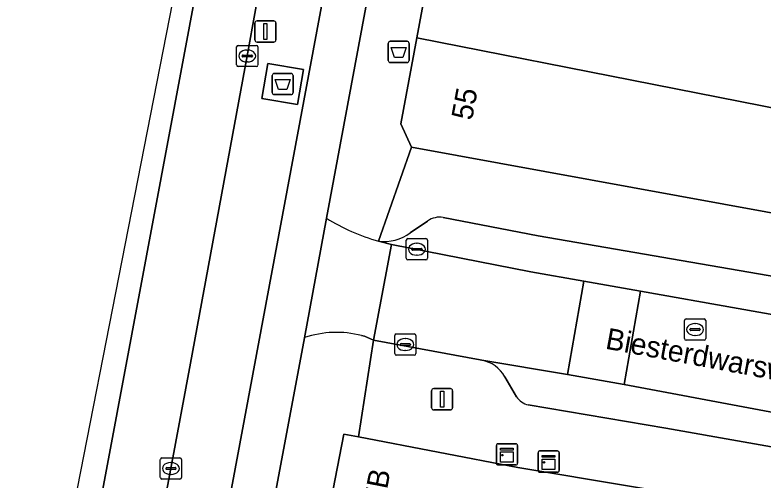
# Model space of a CAD drawing. Extents: x 161838 to 162344, y 381620 to 382160.
# Drawn here: x 161893.72 to 161929.05, y 381932.12 to 381954.06 of the extents above; entities that cross this region are included whole.
import ezdxf

# ---------------------------------------------------------------- set-up
doc = ezdxf.new("R2010")
doc.units = 0
for name, color, linetype in [('IMGEO_Afval_apart_plaats', 7, 'Continuous'), ('IMGEO_Afvalbak', 7, 'Continuous'), ('IMGEO_Berm_open', 7, 'Continuous'), ('IMGEO_Fietspad_gesloten', 7, 'Continuous'), ('IMGEO_Kast', 7, 'Continuous'), ('IMGEO_Kolk', 7, 'Continuous'), ('IMGEO_Lichtmast', 7, 'Continuous'), ('IMGEO_Muur', 7, 'Continuous'), ('IMGEO_Openbare_ruimte_label', 7, 'Continuous'), ('IMGEO_OVBaan_gesloten', 7, 'Continuous'), ('IMGEO_Pand', 7, 'Continuous'), ('IMGEO_Pand_nummerreeks', 7, 'Continuous'), ('IMGEO_Parkeervlak_open', 7, 'Continuous'), ('IMGEO_Rijbaan_lokaal_gesloten', 7, 'Continuous'), ('IMGEO_Rijbaan_lokaal_open', 7, 'Continuous'), ('IMGEO_Rioolput', 7, 'Continuous'), ('IMGEO_Voetpad_gesloten', 7, 'Continuous'), ('IMGEO_Voetpad_open', 7, 'Continuous')]:
    doc.layers.add(name, color=color, linetype=linetype)

msp = doc.modelspace()

# ---------------------------------------------------------------- linework, layer by layer
at = {"layer": 'IMGEO_Afval_apart_plaats'}
for p, q in [((161905.866, 381950.4), (161905.866, 381951.2)), ((161905.866, 381951.2), (161905.866, 381950.4)), ((161905.966, 381951.3), (161906.756, 381951.3)), ((161906.756, 381951.3), (161905.966, 381951.3)), ((161906.856, 381951.2), (161906.856, 381950.4)), ((161906.856, 381950.4), (161906.856, 381951.2)), ((161906.756, 381950.3), (161905.966, 381950.3)), ((161905.966, 381950.3), (161906.756, 381950.3))]:
    msp.add_line(p, q, dxfattribs=at)
msp.add_lwpolyline([(161906.009, 381951.014), (161906.713, 381951.014), (161906.564, 381950.544), (161906.158, 381950.544), (161906.009, 381951.014)], dxfattribs=at)
for centre, start, end in [((161905.966, 381951.2), 90, 180), ((161905.966, 381951.2), 90, 180), ((161906.756, 381951.2), 0, 90), ((161906.756, 381951.2), 360, 90), ((161905.966, 381950.4), 180, 270), ((161905.966, 381950.4), 180, 270), ((161906.756, 381950.4), 270, 0), ((161906.756, 381950.4), 270, 0)]:
    msp.add_arc(centre, 0.1, start, end, dxfattribs=at)
at = {"layer": 'IMGEO_Afvalbak'}
for p, q in [((161911.343, 381951.915), (161911.343, 381952.715)), ((161911.343, 381952.715), (161911.343, 381951.915)), ((161911.443, 381952.815), (161912.233, 381952.815)), ((161912.233, 381952.815), (161911.443, 381952.815)), ((161912.333, 381952.715), (161912.333, 381951.915)), ((161912.333, 381951.915), (161912.333, 381952.715)), ((161912.233, 381951.815), (161911.443, 381951.815)), ((161911.443, 381951.815), (161912.233, 381951.815))]:
    msp.add_line(p, q, dxfattribs=at)
msp.add_lwpolyline([(161911.486, 381952.529), (161912.19, 381952.529), (161912.041, 381952.059), (161911.635, 381952.059), (161911.486, 381952.529)], dxfattribs=at)
for centre, start, end in [((161911.443, 381952.715), 90, 180), ((161911.443, 381952.715), 90, 180), ((161912.233, 381952.715), 0, 90), ((161912.233, 381952.715), 360, 90), ((161911.443, 381951.915), 180, 270), ((161911.443, 381951.915), 180, 270), ((161912.233, 381951.915), 270, 0), ((161912.233, 381951.915), 270, 0)]:
    msp.add_arc(centre, 0.1, start, end, dxfattribs=at)
at = {"layer": 'IMGEO_Berm_open'}
for points in [[(161897.858, 381899.101), (161916.698, 382000), (161921.558, 382026.031), (161926.346, 382051.921)], [(161905.11, 381954.479), (161905.076, 381954.299), (161904.686, 381952.125), (161903.787, 381947.27), (161902.001, 381937.624), (161901.082, 381932.662), (161899.202, 381922.742)]]:
    msp.add_lwpolyline(points, dxfattribs=at)
msp.add_lwpolyline([(161905.383, 381950.116), (161905.654, 381951.762), (161907.339, 381951.485), (161907.068, 381949.839)], close=True, dxfattribs=at)
at = {"layer": 'IMGEO_Fietspad_gesloten'}
for points in [[(161897.095, 381883.929), (161899.866, 381898.705), (161907.39, 381938.834), (161908.427, 381944.469), (161918.786, 382000), (161923.625, 382025.943), (161928.95, 382054.459)], [(161926.346, 382051.921), (161921.558, 382026.031), (161916.698, 382000), (161897.858, 381899.101), (161895.081, 381884.229), (161870.207, 381751.91), (161869.854, 381750), (161864.774, 381722.548), (161862.987, 381712.892), (161857.316, 381682.246)]]:
    msp.add_lwpolyline(points, dxfattribs=at)
at = {"layer": 'IMGEO_Kast'}
for p, q in [((161916.452, 381932.904), (161916.452, 381933.745)), ((161916.452, 381933.745), (161916.452, 381932.904)), ((161916.527, 381933.829), (161917.368, 381933.829)), ((161917.368, 381933.829), (161916.527, 381933.829)), ((161917.452, 381933.754), (161917.452, 381932.913)), ((161917.452, 381932.913), (161917.452, 381933.754)), ((161918.42, 381932.564), (161918.42, 381933.405)), ((161918.42, 381933.405), (161918.42, 381932.564)), ((161918.495, 381933.489), (161919.336, 381933.489)), ((161919.336, 381933.489), (161918.495, 381933.489)), ((161919.42, 381933.414), (161919.42, 381932.573)), ((161919.42, 381932.573), (161919.42, 381933.414)), ((161917.377, 381932.829), (161916.536, 381932.829)), ((161916.536, 381932.829), (161917.377, 381932.829)), ((161919.345, 381932.489), (161918.504, 381932.489)), ((161918.504, 381932.489), (161919.345, 381932.489))]:
    msp.add_line(p, q, dxfattribs=at)
for points in [[(161916.647, 381933.619), (161917.247, 381933.619), (161917.247, 381933.534), (161916.647, 381933.534), (161916.647, 381933.619)], [(161916.647, 381933.444), (161917.247, 381933.444), (161917.247, 381932.955), (161916.647, 381932.955), (161916.647, 381933.444)], [(161918.615, 381933.279), (161919.215, 381933.279), (161919.215, 381933.194), (161918.615, 381933.194), (161918.615, 381933.279)], [(161918.615, 381933.104), (161919.215, 381933.104), (161919.215, 381932.615), (161918.615, 381932.615), (161918.615, 381933.104)]]:
    msp.add_lwpolyline(points, dxfattribs=at)
for centre in [(161916.731, 381933.293), (161918.699, 381932.953)]:
    msp.add_circle(centre, 0.0377, dxfattribs=at)
for centre, start, end in [((161916.53, 381933.751), 92.4484, 184.2845), ((161916.53, 381933.751), 92.4484, 184.2845), ((161917.374, 381933.751), 2.4484, 94.2845), ((161917.374, 381933.751), 2.4484, 94.2845), ((161918.498, 381933.411), 92.4484, 184.2845), ((161918.498, 381933.411), 92.4484, 184.2845), ((161919.342, 381933.411), 2.4484, 94.2845), ((161919.342, 381933.411), 2.4484, 94.2845), ((161916.53, 381932.907), 182.4484, 274.2845), ((161916.53, 381932.907), 182.4484, 274.2845), ((161917.374, 381932.907), 272.4484, 4.2845), ((161917.374, 381932.907), 272.4484, 4.2845), ((161918.498, 381932.567), 182.4484, 274.2845), ((161918.498, 381932.567), 182.4484, 274.2845), ((161919.342, 381932.567), 272.4484, 4.2845), ((161919.342, 381932.567), 272.4484, 4.2845)]:
    msp.add_arc(centre, 0.0779, start, end, dxfattribs=at)
at = {"layer": 'IMGEO_Kolk'}
for p, q in [((161904.187, 381951.698), (161904.187, 381952.55)), ((161904.262, 381952.624), (161905.114, 381952.624)), ((161905.188, 381952.55), (161905.188, 381951.698)), ((161904.446, 381952.118), (161904.446, 381952.13)), ((161904.489, 381952.167), (161904.887, 381952.167)), ((161904.675, 381952.404), (161904.7, 381952.404)), ((161904.93, 381952.13), (161904.93, 381952.118)), ((161904.884, 381952.081), (161904.486, 381952.081)), ((161904.698, 381951.844), (161904.673, 381951.844)), ((161905.114, 381951.624), (161904.262, 381951.624)), ((161912.199, 381942.58), (161912.199, 381943.432)), ((161912.274, 381943.506), (161913.126, 381943.506)), ((161912.687, 381943.286), (161912.712, 381943.286)), ((161913.2, 381943.432), (161913.2, 381942.58)), ((161912.458, 381943), (161912.458, 381943.012)), ((161912.896, 381942.963), (161912.498, 381942.963)), ((161912.501, 381943.049), (161912.899, 381943.049)), ((161912.942, 381943.012), (161912.942, 381943)), ((161912.71, 381942.726), (161912.685, 381942.726)), ((161913.126, 381942.506), (161912.274, 381942.506)), ((161911.651, 381938.083), (161911.651, 381938.935)), ((161911.726, 381939.009), (161912.578, 381939.009)), ((161912.139, 381938.789), (161912.164, 381938.789)), ((161912.652, 381938.935), (161912.652, 381938.083)), ((161911.91, 381938.503), (161911.91, 381938.515)), ((161912.348, 381938.466), (161911.95, 381938.466)), ((161911.953, 381938.552), (161912.351, 381938.552)), ((161912.394, 381938.515), (161912.394, 381938.503)), ((161912.578, 381938.009), (161911.726, 381938.009)), ((161912.162, 381938.229), (161912.137, 381938.229)), ((161900.582, 381932.236), (161900.582, 381933.088)), ((161900.657, 381933.162), (161901.509, 381933.162)), ((161901.583, 381933.088), (161901.583, 381932.236)), ((161900.884, 381932.705), (161901.282, 381932.705)), ((161901.07, 381932.942), (161901.095, 381932.942)), ((161900.841, 381932.656), (161900.841, 381932.668)), ((161901.279, 381932.619), (161900.881, 381932.619)), ((161901.093, 381932.382), (161901.068, 381932.382)), ((161901.325, 381932.668), (161901.325, 381932.656)), ((161901.509, 381932.162), (161900.657, 381932.162))]:
    msp.add_line(p, q, dxfattribs=at)
for points in [[(161904.187, 381951.698), (161904.187, 381952.55)], [(161904.262, 381952.624), (161905.114, 381952.624)], [(161905.188, 381952.55), (161905.188, 381951.698)], [(161905.114, 381951.624), (161904.262, 381951.624)], [(161912.199, 381942.58), (161912.199, 381943.432)], [(161912.274, 381943.506), (161913.126, 381943.506)], [(161913.2, 381943.432), (161913.2, 381942.58)], [(161913.126, 381942.506), (161912.274, 381942.506)], [(161911.651, 381938.083), (161911.651, 381938.935)], [(161911.726, 381939.009), (161912.578, 381939.009)], [(161912.652, 381938.935), (161912.652, 381938.083)], [(161912.578, 381938.009), (161911.726, 381938.009)], [(161900.582, 381932.236), (161900.582, 381933.088)], [(161900.657, 381933.162), (161901.509, 381933.162)], [(161901.583, 381933.088), (161901.583, 381932.236)], [(161901.509, 381932.162), (161900.657, 381932.162)]]:
    msp.add_lwpolyline(points, dxfattribs=at)
for centre, radius, start, end in [((161904.264, 381952.548), 0.0765, 91.552, 178.448), ((161904.264, 381952.548), 0.0765, 91.552, 178.448), ((161905.112, 381952.548), 0.0765, 1.552, 88.448), ((161905.112, 381952.548), 0.0765, 1.552, 88.448), ((161904.486, 381952.127), 0.0403, 85.8775, 175.7526), ((161904.483, 381952.117), 0.0366, 178.938, 274.7102), ((161904.887, 381952.124), 0.043, 264.8664, 352.4533), ((161904.891, 381952.129), 0.0386, 1.7309, 96.639), ((161904.264, 381951.7), 0.0765, 181.552, 268.448), ((161904.264, 381951.7), 0.0765, 181.552, 268.448), ((161905.112, 381951.7), 0.0765, 271.552, 358.448), ((161905.112, 381951.7), 0.0765, 271.552, 358.448), ((161912.276, 381943.43), 0.0765, 91.552, 178.448), ((161912.276, 381943.43), 0.0765, 91.552, 178.448), ((161913.124, 381943.43), 0.0765, 1.552, 88.448), ((161913.124, 381943.43), 0.0765, 1.552, 88.448), ((161912.498, 381943.009), 0.0403, 85.8775, 175.7526), ((161912.495, 381942.999), 0.0366, 178.938, 274.7102), ((161912.899, 381943.006), 0.043, 264.8664, 352.4533), ((161912.903, 381943.011), 0.0386, 1.7309, 96.639), ((161912.276, 381942.582), 0.0765, 181.552, 268.448), ((161912.276, 381942.582), 0.0765, 181.552, 268.448), ((161913.124, 381942.582), 0.0765, 271.552, 358.448), ((161913.124, 381942.582), 0.0765, 271.552, 358.448), ((161911.728, 381938.933), 0.0765, 91.552, 178.448), ((161911.728, 381938.933), 0.0765, 91.552, 178.448), ((161912.576, 381938.933), 0.0765, 1.552, 88.448), ((161912.576, 381938.933), 0.0765, 1.552, 88.448), ((161911.95, 381938.512), 0.0403, 85.8775, 175.7526), ((161911.947, 381938.502), 0.0366, 178.938, 274.7102), ((161912.351, 381938.509), 0.043, 264.8664, 352.4533), ((161912.355, 381938.514), 0.0386, 1.7309, 96.639), ((161911.728, 381938.085), 0.0765, 181.552, 268.448), ((161911.728, 381938.085), 0.0765, 181.552, 268.448), ((161912.576, 381938.085), 0.0765, 271.552, 358.448), ((161912.576, 381938.085), 0.0765, 271.552, 358.448), ((161900.659, 381933.086), 0.0765, 91.552, 178.448), ((161900.659, 381933.086), 0.0765, 91.552, 178.448), ((161901.507, 381933.086), 0.0765, 1.552, 88.448), ((161901.507, 381933.086), 0.0765, 1.552, 88.448), ((161900.881, 381932.665), 0.0403, 85.8775, 175.7526), ((161901.286, 381932.667), 0.0386, 1.7309, 96.639), ((161900.878, 381932.655), 0.0366, 178.938, 274.7102), ((161901.282, 381932.662), 0.043, 264.8664, 352.4533), ((161900.659, 381932.238), 0.0765, 181.552, 268.448), ((161900.659, 381932.238), 0.0765, 181.552, 268.448), ((161901.507, 381932.238), 0.0765, 271.552, 358.448), ((161901.507, 381932.238), 0.0765, 271.552, 358.448)]:
    msp.add_arc(centre, radius, start, end, dxfattribs=at)
for centre, major_axis, ratio, start_param, end_param in [((161904.674, 381952.124), (-0.387, 0.002), 0.722429, 4.712389, 7.853982), ((161904.699, 381952.124), (-0.39, 0.002), 0.717154, 1.570796, 4.712389), ((161912.686, 381943.006), (-0.387, 0.002), 0.722429, 4.712389, 7.853982), ((161912.711, 381943.006), (-0.39, 0.002), 0.717154, 1.570796, 4.712389), ((161912.138, 381938.509), (-0.387, 0.002), 0.722429, 4.712389, 7.853982), ((161912.163, 381938.509), (-0.39, 0.002), 0.717154, 1.570796, 4.712389), ((161901.069, 381932.662), (-0.387, 0.002), 0.722429, 4.712389, 7.853982), ((161901.094, 381932.662), (-0.39, 0.002), 0.717154, 1.570796, 4.712389)]:
    msp.add_ellipse(centre, major_axis=major_axis, ratio=ratio, start_param=start_param, end_param=end_param, dxfattribs=at)
at = {"layer": 'IMGEO_Lichtmast'}
for p, q in [((161905.048, 381952.88), (161905.048, 381953.68)), ((161905.048, 381953.68), (161905.048, 381952.88)), ((161905.148, 381953.78), (161905.938, 381953.78)), ((161905.938, 381953.78), (161905.148, 381953.78)), ((161906.038, 381953.68), (161906.038, 381952.88)), ((161906.038, 381952.88), (161906.038, 381953.68)), ((161905.938, 381952.78), (161905.148, 381952.78)), ((161905.148, 381952.78), (161905.938, 381952.78)), ((161913.395, 381935.53), (161913.395, 381936.33)), ((161913.395, 381936.33), (161913.395, 381935.53)), ((161913.495, 381936.43), (161914.285, 381936.43)), ((161914.285, 381936.43), (161913.495, 381936.43)), ((161914.385, 381936.33), (161914.385, 381935.53)), ((161914.385, 381935.53), (161914.385, 381936.33)), ((161914.285, 381935.43), (161913.495, 381935.43)), ((161913.495, 381935.43), (161914.285, 381935.43))]:
    msp.add_line(p, q, dxfattribs=at)
for points in [[(161905.468, 381953.655), (161905.618, 381953.655), (161905.618, 381952.905), (161905.468, 381952.905), (161905.468, 381953.655)], [(161913.815, 381936.305), (161913.965, 381936.305), (161913.965, 381935.555), (161913.815, 381935.555), (161913.815, 381936.305)]]:
    msp.add_lwpolyline(points, dxfattribs=at)
for centre, start, end in [((161905.148, 381953.68), 90, 180), ((161905.148, 381953.68), 90, 180), ((161905.938, 381953.68), 0, 90), ((161905.938, 381953.68), 360, 90), ((161905.148, 381952.88), 180, 270), ((161905.148, 381952.88), 180, 270), ((161905.938, 381952.88), 270, 0), ((161905.938, 381952.88), 270, 0), ((161913.495, 381936.33), 90, 180), ((161913.495, 381936.33), 90, 180), ((161914.285, 381936.33), 0, 90), ((161914.285, 381936.33), 360, 90), ((161913.495, 381935.53), 180, 270), ((161913.495, 381935.53), 180, 270), ((161914.285, 381935.53), 270, 0), ((161914.285, 381935.53), 270, 0)]:
    msp.add_arc(centre, 0.1, start, end, dxfattribs=at)
at = {"layer": 'IMGEO_Muur'}
msp.add_lwpolyline([(161936.778, 381929.475), (161917.463, 381932.711)], dxfattribs=at)
at = {"layer": 'IMGEO_OVBaan_gesloten'}
msp.add_lwpolyline([(161858.651, 381720.96), (161859.425, 381726.158), (161861.132, 381736.231), (161869.606, 381781.344), (161897.211, 381928.16), (161915.531, 382025.949), (161915.767, 382027.092), (161920.812, 382054.098), (161923.657, 382069.694), (161925.944, 382081.248), (161931.886, 382108.929), (161933.831, 382119.131), (161934.302, 382121.796), (161934.443, 382123.117), (161933.101, 382124.399), (161916.93, 382035.129), (161911.481, 382007.357), (161883.773, 381866.122), (161869.795, 381786.79), (161847.814, 381679.325), (161847.327, 381677.629)], dxfattribs=at)
at = {"layer": 'IMGEO_Pand'}
for points in [[(161936.114, 381954.214), (161935.487, 381954.336), (161927.872, 381955.818), (161913.7, 381958.4), (161912.693, 381952.972), (161935.086, 381948.574)], [(161938.4, 381947.726), (161935.048, 381948.364), (161935.086, 381948.574), (161912.693, 381952.972), (161911.942, 381948.927), (161912.446, 381947.826), (161937.628, 381943.237)], [(161928.197, 381930.913), (161917.463, 381932.711), (161909.938, 381934.153), (161909.255, 381934.284), (161908.231, 381929.021), (161916.384, 381927.527), (161921.399, 381925.893), (161921.324, 381925.485), (161925.907, 381923.95), (161926.864, 381923.63)]]:
    msp.add_lwpolyline(points, close=True, dxfattribs=at)
at = {"layer": 'IMGEO_Parkeervlak_open'}
for points in [[(161930.201, 381941.613), (161918.434, 381943.64), (161913.945, 381944.501)], [(161913.205, 381944.337), (161912.384, 381943.787)], [(161910.886, 381943.394), (161911.493, 381943.232), (161918.084, 381941.946), (161920.577, 381941.504), (161923.265, 381941.028), (161932.48, 381939.395)], [(161922.495, 381936.626), (161919.806, 381937.097), (161915.76, 381937.772)], [(161916.858, 381936.994), (161917.405, 381936.049)], [(161946.986, 381932.028), (161922.495, 381936.626)], [(161917.959, 381935.664), (161924.459, 381934.562), (161943.52, 381931.198)]]:
    msp.add_lwpolyline(points, dxfattribs=at)
for centre, radius, start, end in [((161913.764, 381943.568), 0.95, 78.9882, 126.0038), ((161911.172, 381945.354), 1.98, 261.6838, 307.7167), ((161915.461, 381936.186), 1.614, 30.0488, 79.3114), ((161918.146, 381936.524), 0.88, 212.6734, 257.7322)]:
    msp.add_arc(centre, radius, start, end, dxfattribs=at)
at = {"layer": 'IMGEO_Rijbaan_lokaal_gesloten'}
for points in [[(161918.789, 382041.718), (161915.767, 382027.092), (161915.531, 382025.949), (161897.211, 381928.16), (161869.606, 381781.344), (161861.132, 381736.231), (161859.425, 381726.158), (161858.651, 381720.96)], [(161862.533, 381727.211), (161866.175, 381746.944), (161866.739, 381750), (161866.904, 381750.735), (161870.759, 381771.481), (161871.456, 381775.156), (161894.868, 381899.69), (161899.202, 381922.742), (161901.082, 381932.662), (161902.001, 381937.624), (161903.787, 381947.27), (161904.686, 381952.125), (161905.076, 381954.299), (161905.11, 381954.479), (161913.622, 382000), (161917.608, 382021.312), (161917.651, 382021.542), (161920.351, 382034.502), (161920.367, 382034.753)]]:
    msp.add_lwpolyline(points, dxfattribs=at)
at = {"layer": 'IMGEO_Rijbaan_lokaal_open'}
for points in [[(161908.427, 381944.469), (161907.39, 381938.834)], [(161910.088, 381938.932), (161910.232, 381938.9), (161910.655, 381938.724), (161911.493, 381943.232), (161910.886, 381943.394)], [(161956.934, 381934.662), (161956.559, 381934.761), (161948.397, 381936.525), (161945.23, 381937.136), (161936.936, 381938.606), (161936.675, 381938.652), (161932.946, 381939.313), (161932.48, 381939.395), (161923.265, 381941.028), (161922.495, 381936.626), (161946.986, 381932.028), (161947.69, 381931.869)]]:
    msp.add_lwpolyline(points, dxfattribs=at)
for points in [[(161920.577, 381941.504), (161918.084, 381941.946), (161911.493, 381943.232), (161910.655, 381938.724), (161915.69, 381937.784), (161915.76, 381937.772), (161919.806, 381937.097)], [(161919.806, 381937.097), (161922.495, 381936.626), (161923.265, 381941.028), (161920.577, 381941.504)]]:
    msp.add_lwpolyline(points, close=True, dxfattribs=at)
for centre, radius, start, end in [((161913.374, 381952.435), 9.377, 238.1588, 254.6142), ((161908.903, 381934.363), 4.721, 75.4639, 108.6966)]:
    msp.add_arc(centre, radius, start, end, dxfattribs=at)
at = {"layer": 'IMGEO_Rioolput'}
for p, q in [((161925.339, 381938.792), (161925.339, 381939.644)), ((161925.414, 381939.718), (161926.266, 381939.718)), ((161925.827, 381939.498), (161925.852, 381939.498)), ((161926.34, 381939.644), (161926.34, 381938.792)), ((161925.598, 381939.212), (161925.598, 381939.224)), ((161926.036, 381939.175), (161925.638, 381939.175)), ((161925.641, 381939.261), (161926.039, 381939.261)), ((161926.082, 381939.224), (161926.082, 381939.212)), ((161926.266, 381938.718), (161925.414, 381938.718)), ((161925.85, 381938.938), (161925.825, 381938.938))]:
    msp.add_line(p, q, dxfattribs=at)
for points in [[(161925.339, 381938.792), (161925.339, 381939.644)], [(161925.414, 381939.718), (161926.266, 381939.718)], [(161926.34, 381939.644), (161926.34, 381938.792)], [(161926.266, 381938.718), (161925.414, 381938.718)]]:
    msp.add_lwpolyline(points, dxfattribs=at)
for centre, radius, start, end in [((161925.416, 381939.642), 0.0765, 91.552, 178.448), ((161925.416, 381939.642), 0.0765, 91.552, 178.448), ((161926.264, 381939.642), 0.0765, 1.552, 88.448), ((161926.264, 381939.642), 0.0765, 1.552, 88.448), ((161925.638, 381939.221), 0.0403, 85.8775, 175.7526), ((161925.635, 381939.211), 0.0366, 178.938, 274.7102), ((161926.039, 381939.218), 0.043, 264.8664, 352.4533), ((161926.043, 381939.223), 0.0386, 1.7309, 96.639), ((161925.416, 381938.794), 0.0765, 181.552, 268.448), ((161925.416, 381938.794), 0.0765, 181.552, 268.448), ((161926.264, 381938.794), 0.0765, 271.552, 358.448), ((161926.264, 381938.794), 0.0765, 271.552, 358.448)]:
    msp.add_arc(centre, radius, start, end, dxfattribs=at)
for centre, major_axis, ratio, start_param, end_param in [((161925.826, 381939.218), (-0.387, 0.002), 0.722429, 4.712389, 7.853982), ((161925.851, 381939.218), (-0.39, 0.002), 0.717154, 1.570796, 4.712389)]:
    msp.add_ellipse(centre, major_axis=major_axis, ratio=ratio, start_param=start_param, end_param=end_param, dxfattribs=at)
at = {"layer": 'IMGEO_Voetpad_gesloten'}
msp.add_lwpolyline([(161907.339, 381951.485), (161905.654, 381951.762), (161905.383, 381950.116), (161907.068, 381949.839)], close=True, dxfattribs=at)
at = {"layer": 'IMGEO_Voetpad_open'}
for points in [[(161928.95, 382054.459), (161923.625, 382025.943), (161918.786, 382000), (161908.427, 381944.469)], [(162044.198, 381987.972), (162027.763, 381976.315), (162027.675, 381976.439), (162023.633, 381973.703), (162017.37, 381969.238), (162016.075, 381968.353), (162010.268, 381964.214), (162004.459, 381960.074), (162003.552, 381959.398), (161999.988, 381956.857), (161997.98, 381955.381), (161997.314, 381955), (161991.394, 381951.62), (161990.45, 381950.969), (161985.242, 381948.014), (161980.473, 381945.309), (161975.721, 381942.613), (161974.954, 381942.172), (161969.673, 381939.049), (161967.538, 381937.787), (161959.912, 381939.177), (161958.703, 381939.397), (161937.628, 381943.237), (161912.446, 381947.826)], [(161910.886, 381943.394), (161912.446, 381947.826), (161911.942, 381948.927), (161912.693, 381952.972), (161913.7, 381958.4), (161914.782, 381964.23), (161915.349, 381964.138), (161915.837, 381966.701), (161915.565, 381967.483), (161915.801, 381968.718), (161916.207, 381968.995), (161916.341, 381969.695), (161916.458, 381970.311), (161916.217, 381971.001), (161916.486, 381972.41), (161916.906, 381972.696), (161917.384, 381975.201), (161917.835, 381977.569), (161917.554, 381978.377), (161917.819, 381979.768)], [(161912.446, 381947.826), (161910.886, 381943.394)], [(161913.945, 381944.501), (161918.434, 381943.64), (161930.201, 381941.613)], [(161912.384, 381943.787), (161913.205, 381944.337)], [(161907.39, 381938.834), (161899.866, 381898.705), (161897.095, 381883.929), (161872.236, 381751.615), (161871.936, 381750), (161866.402, 381720.165)], [(161901.744, 381895.676), (161902.239, 381898.237), (161902.268, 381898.386), (161903.341, 381903.897), (161904.615, 381910.446), (161904.636, 381910.55), (161908.231, 381929.021), (161909.255, 381934.284), (161909.938, 381934.153), (161910.655, 381938.724), (161910.232, 381938.9), (161910.088, 381938.932)], [(161915.76, 381937.772), (161915.69, 381937.784), (161910.655, 381938.724), (161909.938, 381934.153), (161917.463, 381932.711), (161928.197, 381930.913), (161936.778, 381929.475), (161948.542, 381927.34), (161951.992, 381926.357)], [(161917.405, 381936.049), (161916.858, 381936.994)], [(161943.52, 381931.198), (161924.459, 381934.562), (161917.959, 381935.664)]]:
    msp.add_lwpolyline(points, dxfattribs=at)
for centre, radius, start, end in [((161913.374, 381952.435), 9.377, 238.1588, 254.6142), ((161913.764, 381943.568), 0.95, 78.9882, 126.0038), ((161911.172, 381945.354), 1.98, 261.6838, 307.7167), ((161908.903, 381934.363), 4.721, 75.4639, 108.6966), ((161915.461, 381936.186), 1.614, 30.0488, 79.3114), ((161918.146, 381936.524), 0.88, 212.6734, 257.7322)]:
    msp.add_arc(centre, radius, start, end, dxfattribs=at)

# ---------------------------------------------------------------- texts
at = {"layer": 'IMGEO_Openbare_ruimte_label'}
msp.add_text('Biesterdwarsweg', height=1, rotation=349.5106, dxfattribs=at).set_placement((161921.562, 381938.321))
at = {"layer": 'IMGEO_Pand_nummerreeks'}
for s, rotation, p in [('55', 79.4864, (161915.301, 381949.051)), ('57-57B', 78.988, (161910.638, 381928.298))]:
    msp.add_text(s, height=1, rotation=rotation, dxfattribs=at).set_placement(p)

doc.saveas('drawing.dxf')
